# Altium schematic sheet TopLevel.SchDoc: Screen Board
size A3; SheetNumber: 1; SheetTotal: 1; SheetTitle: Screen Board
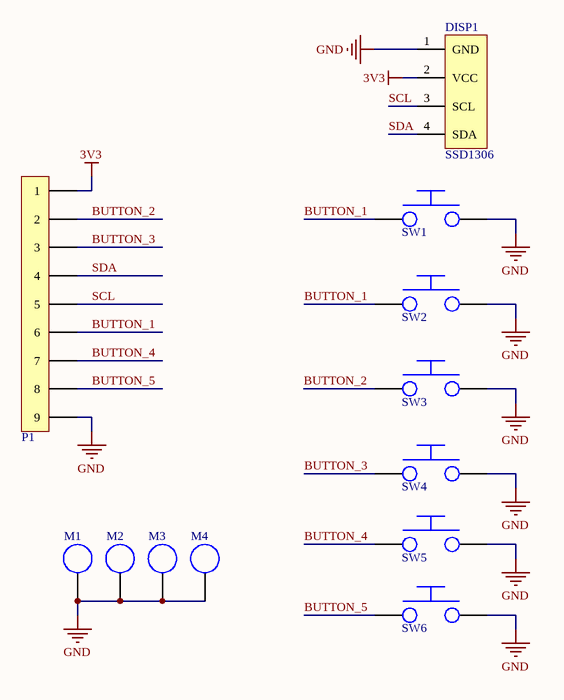
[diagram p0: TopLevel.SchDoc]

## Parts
DISP1  SSD1306  [SSD1306_1.3]
M1  M3 Flat Screw  [M3 Screw]  (value not drawn)
M2  M3 Flat Screw  [M3 Screw]  (value not drawn)
M3  M3 Flat Screw  [M3 Screw]  (value not drawn)
M4  M3 Flat Screw  [M3 Screw]  (value not drawn)
P1  9 Header  [9 Header]  (value not drawn)
SW1  Momentary Button  [TD-19XA]  (value not drawn)
SW2  Momentary Button  [TS1127]  (value not drawn)
SW3  Momentary Button  [Tactile Button 6*6*5mm]  (value not drawn)
SW4  Momentary Button  [Tactile Button 6*6*5mm]  (value not drawn)
SW5  Momentary Button  [Tactile Button 6*6*5mm]  (value not drawn)
SW6  Momentary Button  [Tactile Button 6*6*5mm]  (value not drawn)

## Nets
3V3: DISP1.2(VCC) P1.1
GND: DISP1.1(GND) M1.1 M2.1 M3.1 M4.1 P1.9 SW1.2 SW2.2 SW3.2 SW4.2 SW5.2 SW6.2
BUTTON_1: P1.6 SW1.1 SW2.1
BUTTON_2: P1.2 SW3.1
BUTTON_3: P1.3 SW4.1
BUTTON_4: P1.7 SW5.1
BUTTON_5: P1.8 SW6.1
SCL: DISP1.3(SCL) P1.5
SDA: DISP1.4(SDA) P1.4

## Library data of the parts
DISP1 = SSD1306_1.3: SSD1306 128*64 1.3Inch I2C OLED Module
